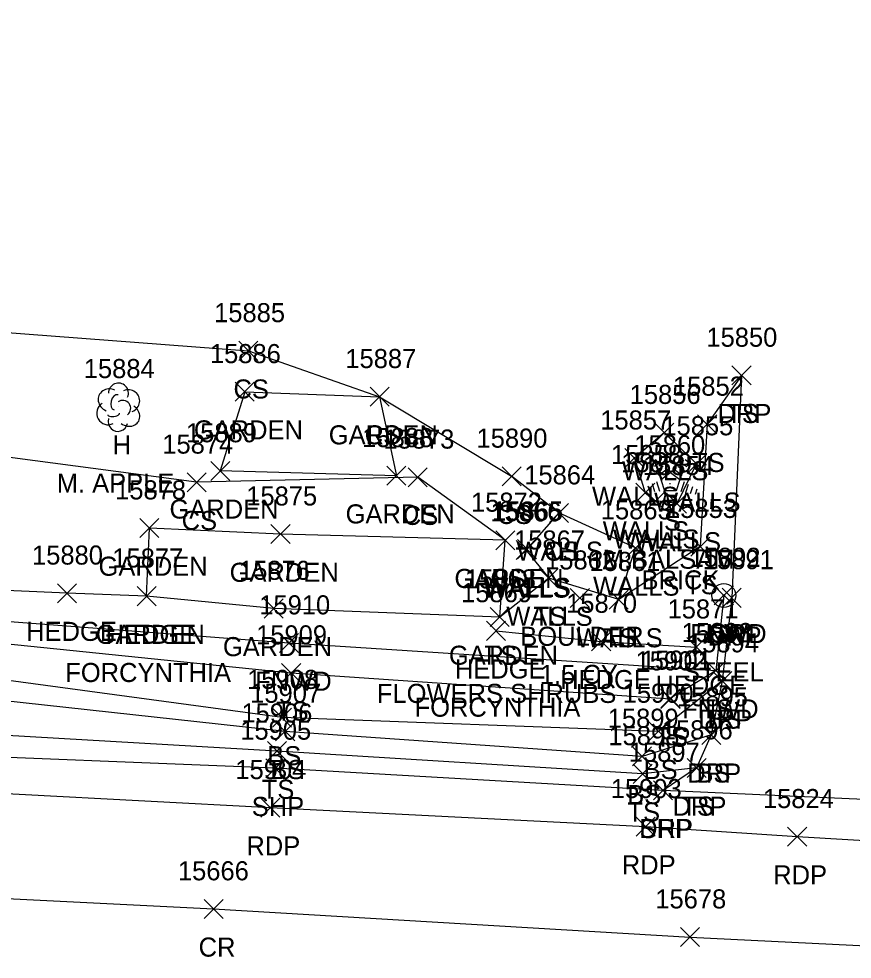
# Model space of a CAD drawing. Extents: x 1606530 to 1613020, y 784959 to 789666.
# Drawn here: x 1609499.3 to 1609586.7, y 788433.6 to 788532.2 of the extents above; entities that cross this region are included whole.
import ezdxf

# ---------------------------------------------------------------- set-up
doc = ezdxf.new("R2010")
doc.units = 0
for name, color, linetype in [('L_A', 7, 'Continuous'), ('L_C', 7, 'Continuous'), ('L_I', 7, 'Continuous'), ('L_TIC', 7, 'Continuous'), ('LAHR', 7, 'Continuous'), ('LAPB', 7, 'Continuous'), ('LELB', 7, 'Continuous'), ('LFNC', 7, 'Continuous'), ('LTC', 7, 'Continuous'), ('LTD', 7, 'Continuous'), ('LWS', 7, 'Continuous'), ('P_A', 7, 'Continuous'), ('P_I', 7, 'Continuous'), ('P_TIC', 7, 'Continuous'), ('PET', 7, 'Continuous'), ('PRC', 7, 'Continuous'), ('PSP', 7, 'Continuous'), ('R_A', 7, 'Continuous'), ('R_I', 7, 'Continuous'), ('R_TIC', 7, 'Continuous'), ('RDP', 7, 'Continuous'), ('RGP', 7, 'Continuous')]:
    doc.layers.add(name, color=color, linetype=linetype)

msp = doc.modelspace()

# ---------------------------------------------------------------- linework, layer by layer
at = {"layer": 'L_TIC'}
for points in [[(1609522.404, 788496.356), (1609524.404, 788498.356)], [(1609524.404, 788496.356), (1609522.404, 788498.356)], [(1609574.12, 788493.783), (1609576.12, 788495.783)], [(1609576.12, 788493.783), (1609574.12, 788495.783)], [(1609522.017, 788492.064), (1609524.017, 788494.064)], [(1609524.017, 788492.064), (1609522.017, 788494.064)], [(1609522.017, 788492.064), (1609524.017, 788494.064)], [(1609524.017, 788492.064), (1609522.017, 788494.064)], [(1609536.166, 788491.546), (1609538.166, 788493.546)], [(1609538.166, 788491.546), (1609536.166, 788493.546)], [(1609536.166, 788491.546), (1609538.166, 788493.546)], [(1609538.166, 788491.546), (1609536.166, 788493.546)], [(1609570.524, 788488.651), (1609572.524, 788490.651)], [(1609572.524, 788488.651), (1609570.524, 788490.651)], [(1609566.041, 788487.787), (1609568.041, 788489.787)], [(1609568.041, 788487.787), (1609566.041, 788489.787)], [(1609562.9, 788485.106), (1609564.9, 788487.106)], [(1609564.9, 788485.106), (1609562.9, 788487.106)], [(1609569.415, 788484.498), (1609571.415, 788486.498)], [(1609571.415, 788484.498), (1609569.415, 788486.498)], [(1609519.461, 788483.768), (1609521.461, 788485.768)], [(1609521.461, 788483.768), (1609519.461, 788485.768)], [(1609519.461, 788483.768), (1609521.461, 788485.768)], [(1609521.461, 788483.768), (1609519.461, 788485.768)], [(1609516.969, 788482.578), (1609518.969, 788484.578)], [(1609518.969, 788482.578), (1609516.969, 788484.578)], [(1609537.934, 788483.26), (1609539.934, 788485.26)], [(1609539.934, 788483.26), (1609537.934, 788485.26)], [(1609540.161, 788483.104), (1609542.161, 788485.104)], [(1609542.161, 788483.104), (1609540.161, 788485.104)], [(1609550.012, 788483.203), (1609552.012, 788485.203)], [(1609552.012, 788483.203), (1609550.012, 788485.203)], [(1609550.012, 788483.203), (1609552.012, 788485.203)], [(1609552.012, 788483.203), (1609550.012, 788485.203)], [(1609564.025, 788481.482), (1609566.025, 788483.482)], [(1609566.025, 788481.482), (1609564.025, 788483.482)], [(1609565.105, 788480.623), (1609567.105, 788482.623)], [(1609567.105, 788480.623), (1609565.105, 788482.623)], [(1609565.105, 788480.623), (1609567.105, 788482.623)], [(1609567.105, 788480.623), (1609565.105, 788482.623)], [(1609567.371, 788480.339), (1609569.371, 788482.339)], [(1609569.371, 788480.339), (1609567.371, 788482.339)], [(1609567.371, 788480.339), (1609569.371, 788482.339)], [(1609569.371, 788480.339), (1609567.371, 788482.339)], [(1609554.977, 788479.354), (1609556.977, 788481.354)], [(1609556.977, 788479.354), (1609554.977, 788481.354)], [(1609554.977, 788479.354), (1609556.977, 788481.354)], [(1609556.977, 788479.354), (1609554.977, 788481.354)], [(1609512.022, 788477.777), (1609514.022, 788479.777)], [(1609514.022, 788477.777), (1609512.022, 788479.777)], [(1609512.022, 788477.777), (1609514.022, 788479.777)], [(1609514.022, 788477.777), (1609512.022, 788479.777)], [(1609525.773, 788477.14), (1609527.773, 788479.14)], [(1609527.773, 788477.14), (1609525.773, 788479.14)], [(1609549.345, 788476.491), (1609551.345, 788478.491)], [(1609551.345, 788476.491), (1609549.345, 788478.491)], [(1609549.345, 788476.491), (1609551.345, 788478.491)], [(1609551.345, 788476.491), (1609549.345, 788478.491)], [(1609551.614, 788475.561), (1609553.614, 788477.561)], [(1609553.614, 788475.561), (1609551.614, 788477.561)], [(1609563.007, 788475.686), (1609565.007, 788477.686)], [(1609565.007, 788475.686), (1609563.007, 788477.686)], [(1609569.796, 788475.834), (1609571.796, 788477.834)], [(1609571.796, 788475.834), (1609569.796, 788477.834)], [(1609551.492, 788475.475), (1609553.492, 788477.475)], [(1609553.492, 788475.475), (1609551.492, 788477.475)], [(1609553.907, 788472.525), (1609555.907, 788474.525)], [(1609555.907, 788472.525), (1609553.907, 788474.525)], [(1609553.907, 788472.525), (1609555.907, 788474.525)], [(1609555.907, 788472.525), (1609553.907, 788474.525)], [(1609503.392, 788470.945), (1609505.392, 788472.945)], [(1609505.392, 788470.945), (1609503.392, 788472.945)], [(1609511.728, 788470.633), (1609513.728, 788472.633)], [(1609513.728, 788470.633), (1609511.728, 788472.633)], [(1609511.728, 788470.633), (1609513.728, 788472.633)], [(1609513.728, 788470.633), (1609511.728, 788472.633)], [(1609572.27, 788470.709), (1609574.27, 788472.709)], [(1609574.27, 788470.709), (1609572.27, 788472.709)], [(1609557.165, 788470.432), (1609559.165, 788472.432)], [(1609559.165, 788470.432), (1609557.165, 788472.432)], [(1609561.247, 788470.274), (1609563.247, 788472.274)], [(1609563.247, 788470.274), (1609561.247, 788472.274)], [(1609561.247, 788470.274), (1609563.247, 788472.274)], [(1609563.247, 788470.274), (1609561.247, 788472.274)], [(1609525.068, 788469.345), (1609527.068, 788471.345)], [(1609527.068, 788469.345), (1609525.068, 788471.345)], [(1609548.767, 788468.441), (1609550.767, 788470.441)], [(1609550.767, 788468.441), (1609548.767, 788470.441)], [(1609548.767, 788468.441), (1609550.767, 788470.441)], [(1609550.767, 788468.441), (1609548.767, 788470.441)], [(1609548.767, 788468.441), (1609550.767, 788470.441)], [(1609550.767, 788468.441), (1609548.767, 788470.441)], [(1609548.365, 788467), (1609550.365, 788469)], [(1609550.365, 788467), (1609548.365, 788469)], [(1609526.656, 788465.724), (1609528.656, 788467.724)], [(1609528.656, 788465.724), (1609526.656, 788467.724)], [(1609559.405, 788465.891), (1609561.405, 788467.891)], [(1609561.405, 788465.891), (1609559.405, 788467.891)], [(1609569.394, 788465.295), (1609571.394, 788467.295)], [(1609571.394, 788465.295), (1609569.394, 788467.295)], [(1609571.433, 788462.819), (1609573.433, 788464.819)], [(1609573.433, 788462.819), (1609571.433, 788464.819)], [(1609571.433, 788462.819), (1609573.433, 788464.819)], [(1609573.433, 788462.819), (1609571.433, 788464.819)], [(1609526.892, 788462.576), (1609528.892, 788464.576)], [(1609528.892, 788462.576), (1609526.892, 788464.576)], [(1609572.104, 788461.745), (1609574.104, 788463.745)], [(1609574.104, 788461.745), (1609572.104, 788463.745)], [(1609566.678, 788459.927), (1609568.678, 788461.927)], [(1609568.678, 788459.927), (1609566.678, 788461.927)], [(1609566.68, 788459.853), (1609568.68, 788461.853)], [(1609568.68, 788459.853), (1609566.68, 788461.853)], [(1609525.943, 788457.91), (1609527.943, 788459.91)], [(1609527.943, 788457.91), (1609525.943, 788459.91)], [(1609526.267, 788456.457), (1609528.267, 788458.457)], [(1609528.267, 788456.457), (1609526.267, 788458.457)], [(1609565.418, 788456.463), (1609567.418, 788458.463)], [(1609567.418, 788456.463), (1609565.418, 788458.463)], [(1609570.955, 788456.093), (1609572.955, 788458.093)], [(1609572.955, 788456.093), (1609570.955, 788458.093)], [(1609525.401, 788454.392), (1609527.401, 788456.392)], [(1609527.401, 788454.392), (1609525.401, 788456.392)], [(1609563.694, 788453.84), (1609565.694, 788455.84)], [(1609565.694, 788453.84), (1609563.694, 788455.84)], [(1609563.756, 788452.011), (1609565.756, 788454.011)], [(1609565.756, 788452.011), (1609563.756, 788454.011)], [(1609569.408, 788452.622), (1609571.408, 788454.622)], [(1609571.408, 788452.622), (1609569.408, 788454.622)]]:
    msp.add_lwpolyline(points, dxfattribs=at)
at = {"layer": 'LAHR'}
for points in [[(1609512.728, 788471.633), (1609504.392, 788471.945), (1609493.173, 788472.425)], [(1609549.365, 788468), (1609560.405, 788466.891), (1609570.394, 788466.295)]]:
    msp.add_lwpolyline(points, dxfattribs=at)
at = {"layer": 'LAPB'}
for points in [[(1609523.017, 788493.064), (1609520.461, 788484.768)], [(1609523.017, 788493.064), (1609537.166, 788492.546), (1609538.934, 788484.26), (1609520.461, 788484.768)], [(1609549.767, 788469.441), (1609526.068, 788470.345), (1609512.728, 788471.633), (1609513.022, 788478.777)], [(1609549.767, 788469.441), (1609550.345, 788477.491), (1609526.773, 788478.14), (1609513.022, 788478.777)]]:
    msp.add_lwpolyline(points, dxfattribs=at)
at = {"layer": 'LELB'}
for points in [[(1609573.104, 788462.745), (1609566.418, 788457.463), (1609526.943, 788458.91), (1609485.798, 788464.47), (1609468.459, 788468.301), (1609458.93, 788473.776), (1609447.101, 788488.325), (1609435.857, 788502.593), (1609441.807, 788532.161)], [(1609572.433, 788463.819), (1609567.678, 788460.927), (1609567.68, 788460.853), (1609527.892, 788463.576), (1609485.869, 788467.848), (1609475.82, 788469.822), (1609463.537, 788483.345), (1609459.293, 788492.187), (1609454.635, 788512.306)], [(1609482.442, 788500.476), (1609523.404, 788497.356), (1609537.166, 788492.546), (1609551.012, 788484.203)], [(1609575.12, 788494.783), (1609571.524, 788489.651), (1609570.796, 788476.834), (1609562.247, 788471.274), (1609554.907, 788473.525), (1609549.767, 788469.441)], [(1609571.955, 788457.093), (1609564.694, 788454.84), (1609527.267, 788457.457), (1609485.995, 788461.949), (1609469.053, 788466.056), (1609455.447, 788471.449), (1609440.54, 788476.414), (1609431.291, 788487.174)], [(1609550.345, 788477.491), (1609541.161, 788484.104), (1609517.969, 788483.578), (1609494.412, 788486.687)], [(1609555.977, 788480.354), (1609551.012, 788484.203)], [(1609570.408, 788453.622), (1609564.756, 788453.011), (1609526.401, 788455.392), (1609486.038, 788457.711), (1609468.834, 788462.107), (1609453.206, 788464.388), (1609423.172, 788463.36), (1609331.819, 788464.93), (1609285.232, 788464.875), (1609232.948, 788461.354), (1609187.317, 788454.569)]]:
    msp.add_lwpolyline(points, dxfattribs=at)
at = {"layer": 'LFNC'}
msp.add_lwpolyline([(1609573.27, 788471.709), (1609572.433, 788463.819), (1609527.656, 788466.724), (1609486.004, 788469.899), (1609480.222, 788489.265), (1609477.205, 788500.85)], dxfattribs=at)
at = {"layer": 'LTC'}
for p, q in [((1609565.801, 788485.72), (1609566.155, 788485.977)), ((1609566.01, 788485.254), (1609566.539, 788485.638)), ((1609568.828, 788485.612), (1609569.377, 788485.212)), ((1609569.199, 788485.96), (1609569.618, 788485.655)), ((1609566.22, 788484.788), (1609566.924, 788485.3)), ((1609566.429, 788484.322), (1609567.308, 788484.96)), ((1609566.654, 788483.867), (1609567.666, 788484.602)), ((1609567.666, 788484.602), (1609568.663, 788483.877)), ((1609568.086, 788484.915), (1609568.895, 788484.326)), ((1609568.457, 788485.263), (1609569.136, 788484.77)), ((1609565.744, 788483.432), (1609566.015, 788482.597)), ((1609566.199, 788483.648), (1609566.53, 788482.629)), ((1609566.654, 788483.867), (1609567.041, 788482.674)), ((1609568.663, 788483.877), (1609568.271, 788482.674)), ((1609569.1, 788483.606), (1609568.762, 788482.567)), ((1609564.833, 788482.999), (1609564.985, 788482.531)), ((1609565.289, 788483.215), (1609565.5, 788482.564)), ((1609568.271, 788482.674), (1609567.041, 788482.674)), ((1609569.545, 788483.356), (1609569.257, 788482.471)), ((1609569.989, 788483.106), (1609569.752, 788482.376)), ((1609570.434, 788482.855), (1609570.247, 788482.281)), ((1609568.233, 788482.174), (1609567.089, 788482.174)), ((1609568.149, 788481.674), (1609567.161, 788481.674)), ((1609568.066, 788481.174), (1609567.234, 788481.174)), ((1609567.982, 788480.674), (1609567.307, 788480.674))]:
    msp.add_line(p, q, dxfattribs=at)
at = {"layer": 'LTD'}
msp.add_line((1609509.735, 788491.494), (1609509.735, 788491.494), dxfattribs=at)
msp.add_line((1609509.735, 788491.494), (1609509.735, 788491.494), dxfattribs=at)
msp.add_arc((1609509.781, 788492.928), 1.047, 335.52715, 180.95627, dxfattribs=at)
for centre, major_axis, ratio, start_param, end_param in [((1609508.943, 788492.16), (1.21, -0.512), 0.895232, 1.570796, 4.712389), ((1609510.776, 788492.077), (-1.141, -0.483), 0.949671, 1.570796, 4.712389), ((1609509.526, 788491.952), (-0.208, -0.792), 0.645439, 3.141593, 6.283185), ((1609508.651, 788490.785), (0.584, -1.042), 0.959034, 3.141593, 6.283185), ((1609510.235, 788491.327), (-0.5, 0.667), 0.989748, 3.141593, 6.283185), ((1609510.735, 788490.661), (-1.09, 0.792), 0.841452, 1.570796, 4.712389), ((1609509.276, 788490.744), (-0.625, -0.083), 0.423636, 0, 3.141593), ((1609509.735, 788489.994), (0.265, 1.061), 0.942809, 1.570796, 4.712389)]:
    msp.add_ellipse(centre, major_axis=major_axis, ratio=ratio, start_param=start_param, end_param=end_param, dxfattribs=at)
at = {"layer": 'LWS'}
for points in [[(1609568.371, 788481.339), (1609570.415, 788485.498), (1609567.041, 788488.787), (1609563.9, 788486.106), (1609565.025, 788482.482), (1609566.105, 788481.623)], [(1609568.371, 788481.339), (1609566.105, 788481.623)], [(1609562.247, 788471.274), (1609564.007, 788476.686), (1609555.977, 788480.354), (1609552.614, 788476.561), (1609552.492, 788476.475), (1609554.907, 788473.525)]]:
    msp.add_lwpolyline(points, dxfattribs=at)
at = {"layer": 'P_TIC'}
for points in [[(1609525.223, 788452.589), (1609527.223, 788454.589)], [(1609527.223, 788452.589), (1609525.223, 788454.589)], [(1609565.898, 788450.268), (1609567.898, 788452.268)], [(1609567.898, 788450.268), (1609565.898, 788452.268)], [(1609524.711, 788448.455), (1609526.711, 788450.455)], [(1609526.711, 788448.455), (1609524.711, 788450.455)], [(1609564.084, 788446.467), (1609566.084, 788448.467)], [(1609566.084, 788446.467), (1609564.084, 788448.467)], [(1609579.961, 788445.419), (1609581.961, 788447.419)], [(1609581.961, 788445.419), (1609579.961, 788447.419)], [(1609518.757, 788437.847), (1609520.757, 788439.847)], [(1609520.757, 788437.847), (1609518.757, 788439.847)], [(1609568.723, 788434.898), (1609570.723, 788436.898)], [(1609570.723, 788434.898), (1609568.723, 788436.898)]]:
    msp.add_lwpolyline(points, dxfattribs=at)
at = {"layer": 'PET'}
msp.add_lwpolyline([(1609713.165, 788438.627), (1609680.929, 788440.448), (1609651.997, 788442.015), (1609625.849, 788443.733), (1609580.961, 788446.419), (1609565.084, 788447.467), (1609525.711, 788449.455), (1609486.159, 788451.542), (1609451.915, 788453.585), (1609423.874, 788454.943), (1609378.56, 788456.924), (1609332.013, 788457.666), (1609286.402, 788456.921), (1609233.035, 788453.523), (1609189.077, 788447.384), (1609175.759, 788445.193), (1609148.778, 788439.997), (1609127.707, 788434.803)], dxfattribs=at)
at = {"layer": 'PRC'}
msp.add_lwpolyline([(1608863.252, 788300.903), (1608901.811, 788322.596), (1608937.609, 788342.722), (1608976.118, 788362.757), (1609017.577, 788382.951), (1609062.579, 788402.235), (1609089.789, 788412.891), (1609118.805, 788421.444), (1609162.845, 788431.752), (1609194.146, 788437.356), (1609237.64, 788442.85), (1609286.897, 788446.16), (1609332.711, 788446.436), (1609379.393, 788445.342), (1609425.621, 788443.432), (1609445.831, 788442.47), (1609477.779, 788440.947), (1609519.757, 788438.847), (1609569.723, 788435.898), (1609601.73, 788434.311), (1609642.39, 788431.817), (1609682.025, 788429.153), (1609726.546, 788426.785)], dxfattribs=at)
at = {"layer": 'PSP'}
msp.add_lwpolyline([(1609713.922, 788443.117), (1609681.225, 788444.652), (1609657.996, 788445.994), (1609646.319, 788446.917), (1609626.337, 788447.989), (1609592.684, 788450.096), (1609566.898, 788451.268), (1609526.223, 788453.589), (1609486.022, 788455.2), (1609451.52, 788457.024), (1609423.816, 788458.463), (1609378.085, 788460.467), (1609331.883, 788461.682), (1609285.229, 788461.605), (1609232.595, 788457.915), (1609188.508, 788451.364), (1609172.5, 788448.52), (1609147.32, 788443.745), (1609126.968, 788439.128), (1609114.118, 788436.455)], dxfattribs=at)
at = {"layer": 'R_TIC'}
for points in [[(1609574.12, 788493.783), (1609576.12, 788495.783)], [(1609576.12, 788493.783), (1609574.12, 788495.783)], [(1609573.092, 788470.463), (1609575.092, 788472.463)], [(1609575.092, 788470.463), (1609573.092, 788472.463)], [(1609572.104, 788461.745), (1609574.104, 788463.745)], [(1609574.104, 788461.745), (1609572.104, 788463.745)], [(1609570.955, 788456.093), (1609572.955, 788458.093)], [(1609572.955, 788456.093), (1609570.955, 788458.093)], [(1609569.408, 788452.622), (1609571.408, 788454.622)], [(1609571.408, 788452.622), (1609569.408, 788454.622)], [(1609565.898, 788450.268), (1609567.898, 788452.268)], [(1609567.898, 788450.268), (1609565.898, 788452.268)]]:
    msp.add_lwpolyline(points, dxfattribs=at)
at = {"layer": 'RDP'}
msp.add_lwpolyline([(1609575.12, 788494.783), (1609574.092, 788471.463), (1609573.104, 788462.745), (1609571.955, 788457.093), (1609570.408, 788453.622), (1609566.898, 788451.268)], dxfattribs=at)
at = {"layer": 'RGP'}
msp.add_line((1609573.27, 788471.709), (1609573.27, 788471.709), dxfattribs=at)
for radius in [1.25, 0.0833]:
    msp.add_circle((1609573.27, 788471.709), radius, dxfattribs=at)

# ---------------------------------------------------------------- texts
at = {"layer": 'L_A'}
for s, p in [('CS', (1609521.845, 788492.356)), ('TS', (1609573.53, 788489.783)), ('GARDEN', (1609517.687, 788488.064)), ('GARDEN', (1609517.687, 788488.064)), ('GARDEN', (1609531.835, 788487.546)), ('CS', (1609535.607, 788487.546)), ('H', (1609509.168, 788486.494)), ('TS', (1609569.934, 788484.651)), ('WALLS', (1609562.585, 788483.787)), ('WALLS', (1609559.444, 788481.106)), ('WALLS', (1609565.959, 788480.498)), ('GARDEN', (1609515.131, 788479.768)), ('GARDEN', (1609515.131, 788479.768)), ('CS', (1609516.41, 788478.578)), ('GARDEN', (1609533.604, 788479.26)), ('CS', (1609539.602, 788479.104)), ('CS', (1609549.453, 788479.203)), ('CS', (1609549.453, 788479.203)), ('S', (1609566.991, 788478.511)), ('WALLS', (1609560.569, 788477.482)), ('WALLS', (1609561.648, 788476.623)), ('WALLS', (1609561.648, 788476.623)), ('WALLS', (1609563.914, 788476.339)), ('WALLS', (1609563.914, 788476.339)), ('WALLS', (1609551.521, 788475.354)), ('CS', (1609554.418, 788475.354)), ('GARDEN', (1609507.691, 788473.777)), ('GARDEN', (1609507.691, 788473.777)), ('GARDEN', (1609521.442, 788473.14)), ('GARDEN', (1609545.015, 788472.491)), ('WALLS', (1609548.157, 788471.561)), ('CS', (1609548.786, 788472.491)), ('WALLS', (1609559.55, 788471.686)), ('TS', (1609569.205, 788471.834)), ('WALLS', (1609548.035, 788471.475)), ('WALLS', (1609550.451, 788468.525)), ('TS', (1609553.317, 788468.525)), ('HEDGE', (1609500.093, 788466.945)), ('GARDEN', (1609507.398, 788466.633)), ('HEDGE', (1609508.429, 788466.633)), ('FNWD', (1609569.734, 788466.709)), ('BOULDER', (1609551.921, 788466.432)), ('WALLS', (1609557.79, 788466.274)), ('TS', (1609560.656, 788466.274)), ('GARDEN', (1609520.738, 788465.345)), ('GARDEN', (1609544.436, 788464.441)), ('GARDEN', (1609544.436, 788464.441)), ('TS', (1609548.177, 788464.441)), ('HEDGE', (1609545.066, 788463)), ('FNWD', (1609524.121, 788461.724)), ('HEDGE', (1609556.106, 788461.891)), ('HEDGE', (1609566.095, 788461.295)), ('FNWD', (1609568.898, 788458.819)), ('TS', (1609570.843, 788458.819)), ('TS', (1609526.301, 788458.576)), ('BS', (1609571.544, 788457.745)), ('TS', (1609566.088, 788455.927)), ('TS', (1609566.089, 788455.853)), ('BS', (1609525.384, 788453.91)), ('BS', (1609525.708, 788452.457)), ('BS', (1609564.859, 788452.463)), ('BS', (1609570.396, 788452.093)), ('TS', (1609524.811, 788450.392)), ('BS', (1609563.135, 788449.84)), ('TS', (1609563.166, 788448.011)), ('TS', (1609568.817, 788448.622))]:
    msp.add_text(s, height=2, dxfattribs=at).set_placement(p)
at = {"layer": 'L_C'}
for s, p in [('M. APPLE', (1609503.31, 788482.494)), ('M.BALSAM', (1609560.566, 788474.511)), ('BRICK', (1609564.639, 788472.339)), ('BRICK', (1609564.639, 788472.339)), ('STEEL', (1609568.986, 788462.709)), ('FORCYNTHIA', (1609504.201, 788462.633)), ('1.5 CY', (1609553.976, 788462.432)), ('FLOWERS SHRUBS', (1609536.885, 788460.441)), ('FLOWERS SHRUBS', (1609536.885, 788460.441)), ('FORCYNTHIA', (1609540.838, 788459))]:
    msp.add_text(s, height=2, dxfattribs=at).set_placement(p)
at = {"layer": 'L_I'}
for s, p in [('15885', (1609519.814, 788500.356)), ('15850', (1609571.444, 788497.783)), ('15886', (1609519.372, 788496.064)), ('15886', (1609519.372, 788496.064)), ('15887', (1609533.576, 788495.546)), ('15887', (1609533.576, 788495.546)), ('15884', (1609506.144, 788494.494)), ('15852', (1609567.934, 788492.651)), ('15856', (1609563.396, 788491.787)), ('15857', (1609560.31, 788489.106)), ('15855', (1609566.825, 788488.498)), ('15889', (1609516.863, 788487.768)), ('15889', (1609516.863, 788487.768)), ('15874', (1609514.378, 788486.578)), ('15888', (1609535.344, 788487.26)), ('15873', (1609537.57, 788487.104)), ('15890', (1609547.335, 788487.203)), ('15890', (1609547.335, 788487.203)), ('15860', (1609563.881, 788486.511)), ('15858', (1609561.435, 788485.482)), ('15859', (1609562.506, 788484.623)), ('15859', (1609562.506, 788484.623)), ('15854', (1609564.781, 788484.339)), ('15854', (1609564.781, 788484.339)), ('15864', (1609552.34, 788483.354)), ('15864', (1609552.34, 788483.354)), ('15878', (1609509.431, 788481.777)), ('15878', (1609509.431, 788481.777)), ('15875', (1609523.183, 788481.14)), ('15872', (1609546.755, 788480.491)), ('15872', (1609546.755, 788480.491)), ('15866', (1609548.799, 788479.475)), ('15865', (1609548.976, 788479.561)), ('15863', (1609560.369, 788479.686)), ('15853', (1609567.206, 788479.834)), ('15867', (1609551.27, 788476.525)), ('15867', (1609551.27, 788476.525)), ('15880', (1609500.715, 788474.945)), ('15877', (1609509.138, 788474.633)), ('15877', (1609509.138, 788474.633)), ('15892', (1609569.679, 788474.709)), ('15862', (1609554.527, 788474.432)), ('15861', (1609559.176, 788474.274)), ('15861', (1609559.176, 788474.274)), ('15876', (1609522.423, 788473.345)), ('15868', (1609546.129, 788472.441)), ('15868', (1609546.129, 788472.441)), ('15868', (1609546.129, 788472.441)), ('15869', (1609545.72, 788471)), ('15910', (1609524.547, 788469.724)), ('15870', (1609556.728, 788469.891)), ('15871', (1609567.371, 788469.295)), ('15893', (1609568.843, 788466.819)), ('15893', (1609568.843, 788466.819)), ('15909', (1609524.215, 788466.576)), ('15894', (1609569.513, 788465.745)), ('15902', (1609564.011, 788463.853)), ('15901', (1609564.576, 788463.927)), ('15908', (1609523.274, 788461.91)), ('15907', (1609523.598, 788460.457)), ('15900', (1609562.662, 788460.463)), ('15895', (1609568.364, 788460.093)), ('15906', (1609522.677, 788458.392)), ('15899', (1609561.096, 788457.84)), ('15898', (1609561.166, 788456.011)), ('15896', (1609566.762, 788456.622))]:
    msp.add_text(s, height=2, dxfattribs=at).set_placement(p)
at = {"layer": 'LTC'}
msp.add_text('.', height=1.037, rotation=270, dxfattribs=at).set_placement((1609567.548, 788483.615))
at = {"layer": 'P_A'}
for s, p in [('SHP', (1609523.758, 788448.589)), ('SHP', (1609564.433, 788446.268)), ('RDP', (1609523.2, 788444.455)), ('RDP', (1609562.572, 788442.467)), ('RDP', (1609578.45, 788441.419)), ('CR', (1609518.19, 788433.847))]:
    msp.add_text(s, height=2, dxfattribs=at).set_placement(p)
at = {"layer": 'P_I'}
for s, p in [('15905', (1609522.554, 788456.589)), ('15897', (1609563.308, 788454.268)), ('15904', (1609522.042, 788452.455)), ('15903', (1609561.415, 788450.467)), ('15824', (1609577.371, 788449.419)), ('15666', (1609516.017, 788441.847)), ('15678', (1609566.085, 788438.898))]:
    msp.add_text(s, height=2, dxfattribs=at).set_placement(p)
at = {"layer": 'R_A'}
for s, p in [('DRP', (1609572.609, 788489.783)), ('GP', (1609571.703, 788466.709)), ('DRP', (1609571.58, 788466.463)), ('DRP', (1609570.592, 788457.745)), ('DRP', (1609569.443, 788452.093)), ('DRP', (1609567.896, 788448.622)), ('DRP', (1609564.386, 788446.268))]:
    msp.add_text(s, height=2, dxfattribs=at).set_placement(p)
at = {"layer": 'R_I'}
for s, p in [('15850', (1609571.444, 788497.783)), ('15892', (1609569.679, 788474.709)), ('15891', (1609571.069, 788474.463)), ('15894', (1609569.513, 788465.745)), ('15895', (1609568.364, 788460.093)), ('15896', (1609566.762, 788456.622)), ('15897', (1609563.308, 788454.268))]:
    msp.add_text(s, height=2, dxfattribs=at).set_placement(p)

doc.saveas('drawing.dxf')
